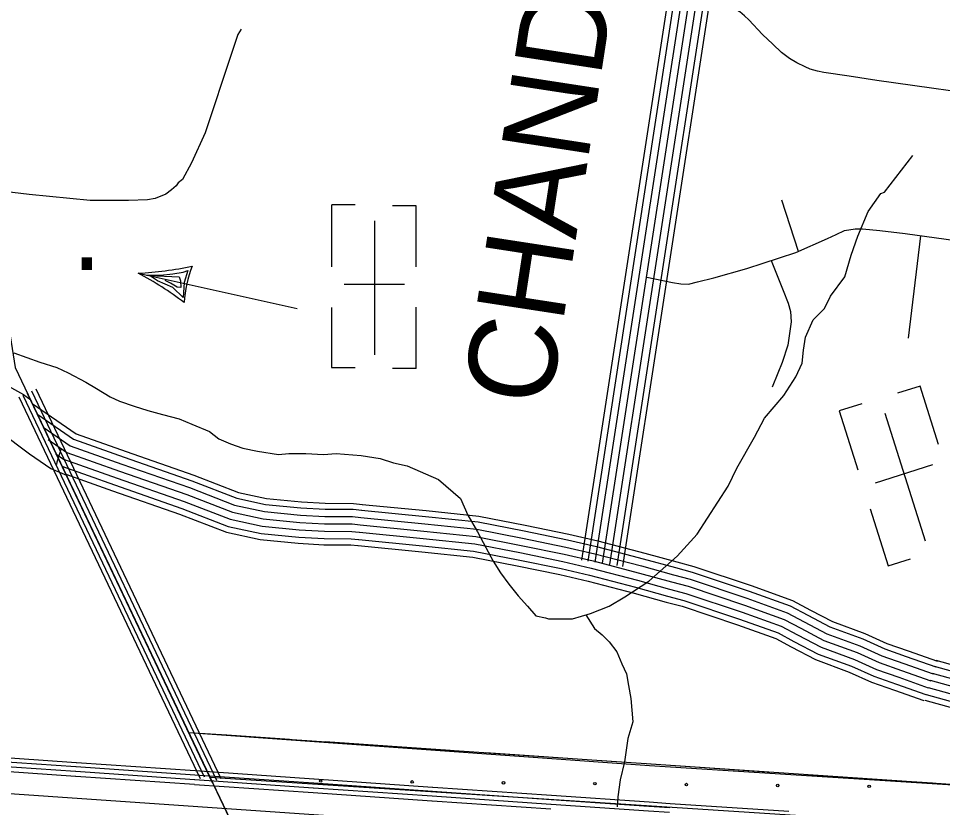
# Model space of a CAD drawing. Extents: x 1788175 to 1969470, y 584502 to 738744.
# Drawn here: x 1799965 to 1803852, y 668600 to 671917 of the extents above; entities that cross this region are included whole.
import ezdxf

# ---------------------------------------------------------------- set-up
doc = ezdxf.new("R2010")
doc.units = 0
for name, color, linetype in [('DESIGN - EROSION CONTROL - Devices', 7, 'Continuous'), ('DESIGN - ROW - Right-of-Way and Easement Labels', 7, 'Continuous'), ('DESIGN - SCRATCH - User 1', 7, 'Continuous'), ('DESIGN - TRANSPORTATION - Text', 7, 'Continuous'), ('DESIGN - UTILITIES - Cable (Overhead) with Text', 7, 'Continuous'), ('DESIGN - UTILITIES - Cable (Underground) with Text', 7, 'Continuous'), ('SURVEY - CENTERLINE - Preliminary', 7, 'Continuous'), ('SURVEY - CONTROL with Text', 7, 'Continuous'), ('SURVEY - DRAINAGE - Natural Features', 7, 'Continuous'), ('SURVEY - TRANSPORTATION - Roads', 7, 'Continuous'), ('SURVEY - VEGETATION - Features with Text', 7, 'Continuous')]:
    doc.layers.add(name, color=color, linetype=linetype)

msp = doc.modelspace()

# ---------------------------------------------------------------- linework, layer by layer
at = {"layer": 'DESIGN - EROSION CONTROL - Devices'}
for centre in [(1801236.5, 668710.8), (1801621, 668707.1), (1802005.6, 668703.4), (1802390.1, 668699.6), (1802774.7, 668695.9), (1803159.2, 668692.2), (1803543.8, 668688.4)]:
    msp.add_circle(centre, 5.28, dxfattribs=at)
at = {"layer": 'DESIGN - SCRATCH - User 1'}
for points in [[(1808664.9, 668387), (1806557.8, 668530), (1805384.9, 668598.1), (1804466.6, 668656.6), (1803677.1, 668706.8), (1802620.2, 668775.3), (1800681.4, 668914), (1800770.3, 668727.1)], [(1800770.3, 668727.1), (1809434.2, 668164.9), (1810234.9, 668118.5)]]:
    msp.add_lwpolyline(points, dxfattribs=at)
at = {"layer": 'DESIGN - TRANSPORTATION - Text'}
for points in [[(1802950.4, 669950.2), (1802986.8, 670026.5), (1803061, 670156.3), (1803103.1, 670236.1), (1803185.2, 670331.9), (1803235.3, 670409.8), (1803261.4, 670467.7), (1803267.5, 670521.7), (1803275.6, 670577.6), (1803307.7, 670649.5), (1803355.7, 670697.4), (1803381.8, 670749.3), (1803441.9, 670831.2), (1803468, 670921), (1803496.1, 671000.9), (1803540.3, 671104.8), (1803592.4, 671180.6), (1803608.4, 671186.6), (1803727.6, 671341)], [(1799945.3, 670510.8), (1800055.3, 670471.2), (1800125.8, 670449.2), (1800174.2, 670427.2), (1800249, 670387.5), (1800293, 670361.1), (1800350.3, 670325.9), (1800389.9, 670308.3), (1800451.5, 670286.3), (1800508.8, 670268.7), (1800570.4, 670251.1), (1800640.8, 670233.5), (1800693.7, 670211.5), (1800768.5, 670180.6), (1800808.1, 670149.8), (1800856.5, 670127.8), (1800909.4, 670110.2), (1800971, 670097), (1801059, 670083.8), (1801103.1, 670088.2), (1801173.5, 670088.2), (1801248.3, 670083.8), (1801301.2, 670088.2), (1801406.8, 670079.4), (1801486.1, 670066.2), (1801543.3, 670048.6), (1801600.5, 670035.4), (1801732.6, 669978.1), (1801825, 669898.9), (1801855.9, 669828.5), (1801895.5, 669758), (1801930.7, 669692), (1801961.5, 669634.8), (1801992.3, 669586.3), (1802027.5, 669537.9), (1802067.2, 669489.5), (1802106.8, 669445.5), (1802142, 669405.8), (1802181.6, 669397), (1802194.8, 669392.6), (1802230.1, 669392.6), (1802296.1, 669392.6), (1802370.9, 669414.6), (1802450.2, 669445.5), (1802516.2, 669485.1), (1802617.5, 669551.1), (1802736.3, 669656.8), (1802820, 669749.2), (1802950.4, 669950.2)], [(1802352.3, 669409.2), (1802388, 669351.8), (1802419.9, 669325.8), (1802449.8, 669295.8), (1802481.8, 669253.8), (1802503.7, 669203.8), (1802523.6, 669161.8), (1802531.5, 669111.9), (1802541.4, 669057.9), (1802549.3, 668960), (1802529.2, 668890.1), (1802515, 668792.2), (1802496.9, 668716.3), (1802486.8, 668644.4), (1802484, 668602.9)]]:
    msp.add_lwpolyline(points, dxfattribs=at)
at = {"layer": 'DESIGN - UTILITIES - Cable (Overhead) with Text'}
for p, q in [((1800469.1, 670845.4), (1801137.4, 670698)), ((1800503.5, 670837.7), (1800562, 670837.8)), ((1800550.3, 670814.4), (1800516.1, 670836)), ((1800516.1, 670836), (1800641.7, 670830)), ((1800562, 670837.8), (1800614.1, 670842.6)), ((1800614.1, 670842.6), (1800658.1, 670850.3)), ((1800641.7, 670830), (1800646.8, 670813.8)), ((1800658.1, 670850.3), (1800677.9, 670856.7)), ((1800677.9, 670856.7), (1800662.6, 670807)), ((1800614.4, 670785.1), (1800550.3, 670814.4)), ((1800604.4, 670803.6), (1800581.9, 670815)), ((1800633.3, 670787.4), (1800604.4, 670803.6)), ((1800646.8, 670813.8), (1800648.3, 670786.3)), ((1800662.6, 670807), (1800658.4, 670743.9)), ((1800658.4, 670743.9), (1800614.4, 670785.1)), ((1800648.3, 670786.3), (1800633.3, 670787.4))]:
    msp.add_line(p, q, dxfattribs=at)
for centre, radius, start, end in [((1800378.5, 672395), 1552.3, 273.3481, 281.7759), ((1801192.7, 670685.8), 532.3, 159.1314, 175.9898), ((1799824.3, 669618.1), 1386.4, 52.8398, 62.2784)]:
    msp.add_arc(centre, radius, start, end, dxfattribs=at)
at = {"layer": 'DESIGN - UTILITIES - Cable (Underground) with Text'}
for p, q in [((1801282.4, 671132.8), (1801282.4, 670872)), ((1801382, 671132.8), (1801283, 671132.8)), ((1801638.7, 671128.9), (1801539, 671128.9)), ((1801638.6, 670872.1), (1801638.6, 671128.9)), ((1801588.6, 670797.7), (1801335, 670797.7)), ((1801282.4, 670701), (1801282.4, 670449.6)), ((1801638.6, 670445.6), (1801638.6, 670703.7)), ((1801282.5, 670449.6), (1801380.8, 670449.6)), ((1801638.5, 670445.6), (1801539, 670445.6)), ((1803758.5, 670370.8), (1803663.3, 670340.8)), ((1803835.7, 670126), (1803758.4, 670370.8)), ((1803512.5, 670297.3), (1803418, 670267.5)), ((1803417.5, 670267.3), (1803496, 670018.6)), ((1803810.4, 670040), (1803568.5, 669963.6)), ((1803547.4, 669855.6), (1803623.2, 669615.8)), ((1803623.3, 669615.8), (1803717, 669645.4))]:
    msp.add_line(p, q, dxfattribs=at)
for points in [[(1801463.3, 671065.4), (1801463.3, 670502.4)], [(1803610.3, 670257.5), (1803779.8, 669720.7)]]:
    msp.add_lwpolyline(points, dxfattribs=at)
at = {"layer": 'SURVEY - CENTERLINE - Preliminary'}
for points in [[(1820911.6, 669976.1), (1819959.6, 669862.9), (1819285.6, 669778.9), (1818471.7, 669687.3), (1818197.7, 669646.1), (1817901.7, 669609), (1817647.6, 669569.8), (1817303.6, 669516.8), (1816595.4, 669363), (1813251.8, 668401.6), (1812821.5, 668274.9), (1812669.5, 668231.4), (1812114.7, 668085.6), (1811965.2, 668057.6), (1811725.2, 668016.3), (1811385.2, 667981.3), (1811049.3, 667954.3), (1810455.5, 667960), (1806509.9, 668228.8), (1805310.6, 668298.1), (1804431.1, 668354.5), (1803641.6, 668404.7), (1802608.2, 668471.6), (1798199.8, 668776.1)], [(1799709.4, 668823.7), (1800208.2, 668789.2)], [(1799706.8, 668786.2), (1800205.6, 668751.8)], [(1799708.2, 668806.2), (1800207, 668771.7)], [(1800207.9, 668771.7), (1800706.7, 668737.2)], [(1800209.1, 668789.1), (1800707.9, 668754.7)], [(1799706.3, 668765.9), (1800205.2, 668731.5)], [(1800206.1, 668731.4), (1800704.9, 668697)], [(1800206.6, 668751.7), (1800705.4, 668717.3)], [(1800707.6, 668737.2), (1801206.5, 668702.7)], [(1800708.9, 668754.6), (1801207.7, 668720.2)], [(1800705.8, 668696.9), (1801204.6, 668662.4)], [(1800706.3, 668717.2), (1801205.1, 668682.7)], [(1801207.4, 668702.6), (1801706.2, 668668.2)], [(1801208.6, 668720.1), (1801707.4, 668685.6)], [(1801205.5, 668662.4), (1801704.3, 668627.9)], [(1801206, 668682.7), (1801704.8, 668648.2)], [(1801707.1, 668668.1), (1802205.9, 668633.6)], [(1801708.3, 668685.6), (1802207.1, 668651.1)], [(1802208, 668651), (1802618.3, 668622.7), (1802706.2, 668617)], [(1801705.2, 668627.8), (1802204, 668593.4)], [(1801705.7, 668648.1), (1802204.5, 668613.7)], [(1802205.4, 668613.6), (1802615.8, 668585.3), (1802703.8, 668579.6)], [(1802206.8, 668633.6), (1802617.1, 668605.2), (1802705, 668599.5)], [(1802707.1, 668616.9), (1803206, 668584.7)]]:
    msp.add_lwpolyline(points, dxfattribs=at)
at = {"layer": 'SURVEY - CONTROL with Text'}
for points in [[(1797699.2, 670443), (1797810.6, 670429.8), (1798058.7, 670432.9), (1798127.3, 670439.7), (1798206.8, 670457.6), (1798263.5, 670474.6), (1798354.5, 670516.8), (1798434, 670547.4), (1798470.8, 670557.1), (1798572, 670579.1), (1798685, 670605.8), (1798773.7, 670598.8), (1798911.1, 670598.4), (1799115.6, 670547.7), (1799248.6, 670545.4), (1799466, 670515.5), (1799572.7, 670490.6), (1799661.8, 670472.5), (1799740.7, 670455.6), (1799813.4, 670416.8), (1799884.2, 670392.3), (1799986.1, 670335.4), (1800016.6, 670312.8)], [(1800022.4, 670298.5), (1800208, 670170.5), (1800418.6, 670095.9), (1800703.4, 669996.8), (1800890.2, 669924.2), (1801008.3, 669898.4), (1801155.5, 669884.6), (1801255.5, 669878.6), (1801373.8, 669878.2), (1801412.2, 669873.9)], [(1800046.7, 670251.8), (1800196.6, 670148.3), (1800410.4, 670072.6), (1800694.8, 669973.6), (1800883.1, 669900.5), (1801004.5, 669874), (1801153.6, 669860), (1801254.8, 669853.9), (1801372.4, 669853.5), (1801409.4, 669849.3)], [(1799885.5, 670179.7), (1800011.5, 670086.1), (1800101.6, 670024.4), (1800167.6, 669996.8)], [(1800073.6, 670195.5), (1800182.4, 670120.4), (1800400.1, 670043.3), (1800684.1, 669944.5), (1800874.1, 669870.7), (1800999.7, 669843.3), (1801151.3, 669829.1), (1801253.8, 669822.9), (1801370.6, 669822.5), (1801405.9, 669818.5)], [(1800090.2, 670146.4), (1800168.2, 670092.6), (1800389.8, 670014.1), (1800673.4, 669915.4), (1800865.1, 669840.9), (1800995, 669812.6), (1801148.9, 669798.2), (1801252.8, 669791.9), (1801368.8, 669791.5), (1801402.4, 669787.7)], [(1800122.7, 670086.3), (1800153.9, 670064.7), (1800379.6, 669984.8), (1800662.7, 669886.3), (1800856.1, 669811.1), (1800990.2, 669781.9), (1801146.5, 669767.2), (1801251.8, 669760.9), (1801367, 669760.6), (1801398.9, 669756.9)], [(1800147.7, 670034.1), (1800369.3, 669955.6), (1800652, 669857.2), (1800847.2, 669781.4), (1800985.4, 669751.2), (1801144.1, 669736.3), (1801250.8, 669729.9), (1801365.2, 669729.6), (1801395.4, 669726.1)], [(1800163.9, 670001), (1800360.8, 669931.3), (1800643.1, 669833), (1800839.7, 669756.7), (1800981.5, 669725.7), (1801142.1, 669710.7), (1801250, 669704.2), (1801363.7, 669703.8), (1801392.5, 669700.6)], [(1801410.7, 669874), (1801679.5, 669848.2), (1801902.2, 669824.5), (1802096.9, 669786.5), (1802279.7, 669749), (1802402.8, 669720.6), (1802599.9, 669669), (1802734.9, 669631.8), (1802806.8, 669612.6), (1803047.5, 669532.3), (1803221.7, 669469.4), (1803296.7, 669429.5), (1803389, 669381.1), (1803526, 669330.9), (1803618.4, 669289.3), (1803707.9, 669257.9), (1803831.8, 669214.4)], [(1801405.4, 669818.6), (1801673.9, 669792.8), (1801893.9, 669769.4), (1802086, 669731.9), (1802267.8, 669694.6), (1802389.5, 669666.5), (1802585.4, 669615.2), (1802720.3, 669578), (1802790.8, 669559.2), (1803029.2, 669479.7), (1803199, 669418.4), (1803270.6, 669380.2), (1803366.4, 669330.1), (1803505, 669279.2), (1803597.7, 669237.5), (1803689.5, 669205.4), (1803813.3, 669161.8)], [(1801408.4, 669849.4), (1801677, 669823.6), (1801898.5, 669800), (1802092.1, 669762.3), (1802274.4, 669724.9), (1802396.9, 669696.6), (1802593.5, 669645.1), (1802728.4, 669607.9), (1802799.7, 669588.9), (1803039.4, 669509), (1803211.7, 669446.8), (1803285.1, 669407.6), (1803378.9, 669358.5), (1803516.7, 669308), (1803609.3, 669266.3), (1803699.8, 669234.6), (1803823.6, 669191.1)], [(1801402.4, 669787.7), (1801670.7, 669761.9), (1801889.3, 669738.7), (1802079.9, 669701.5), (1802261.2, 669664.3), (1802382.1, 669636.4), (1802577.4, 669585.3), (1802712.2, 669548.1), (1802781.9, 669529.5), (1803019, 669450.4), (1803186.4, 669390), (1803256.1, 669352.8), (1803353.8, 669301.6), (1803493.3, 669250.5), (1803586.2, 669208.7), (1803679.2, 669176.1), (1803803, 669132.6)], [(1801399.5, 669756.9), (1801667.6, 669731.1), (1801884.6, 669708), (1802073.8, 669671.1), (1802254.6, 669634), (1802374.7, 669606.3), (1802569.3, 669555.3), (1802704.1, 669518.1), (1802773, 669499.8), (1803008.9, 669421.1), (1803173.8, 669361.6), (1803241.7, 669325.4), (1803341.2, 669273.2), (1803481.6, 669221.8), (1803574.7, 669179.8), (1803669, 669146.9), (1803792.7, 669103.3)], [(1801396.5, 669726), (1801664.5, 669700.2), (1801880, 669677.3), (1802067.7, 669640.7), (1802248, 669603.7), (1802367.3, 669576.2), (1802561.3, 669525.4), (1802696, 669488.2), (1802764.1, 669470), (1802998.7, 669391.8), (1803161.2, 669333.2), (1803227.2, 669298), (1803328.6, 669244.8), (1803469.8, 669193.1), (1803563.2, 669151), (1803658.7, 669117.6), (1803782.4, 669074.1)], [(1801394, 669700.4), (1801661.9, 669674.7), (1801876.2, 669651.9), (1802062.7, 669615.5), (1802242.5, 669578.6), (1802361.1, 669551.2), (1802554.6, 669500.5), (1802689.2, 669463.4), (1802756.7, 669445.4), (1802990.3, 669367.5), (1803150.7, 669309.6), (1803215.2, 669275.2), (1803318.2, 669221.3), (1803460.1, 669169.2), (1803553.7, 669127.1), (1803650.2, 669093.3), (1803773.9, 669049.8)], [(1806246.9, 668859.4), (1806111.8, 668890.9), (1805987.6, 668925.9), (1805845.8, 668972.2), (1805765.7, 668999.7), (1805640.3, 669022.3), (1805500, 669039.2), (1804998.6, 669065), (1804704, 669074.3), (1804514.4, 669076.6), (1804346.8, 669094.7), (1804212.1, 669110.2), (1803825.7, 669217.4)], [(1806234.1, 668804.2), (1806097.6, 668835.9), (1805971.1, 668871.6), (1805827.8, 668918.4), (1805751.4, 668944.7), (1805631.9, 668966.2), (1805495.1, 668982.7), (1804996.3, 669008.3), (1804702.8, 669017.6), (1804511, 669019.9), (1804340.5, 669038.4), (1804201.2, 669054.4), (1803810.6, 669162.7)], [(1806241.1, 668834.4), (1806105.3, 668866), (1805980.1, 668901.3), (1805837.6, 668947.8), (1805759.2, 668974.7), (1805636.5, 668996.8), (1805497.8, 669013.6), (1804997.6, 669039.3), (1804703.4, 669048.6), (1804512.9, 669050.9), (1804344, 669069.2), (1804207.2, 669084.9), (1803818.8, 669192.6)], [(1806227, 668774), (1806089.9, 668805.9), (1805962, 668841.9), (1805817.9, 668889), (1805743.5, 668914.6), (1805627.3, 668935.5), (1805492.5, 668951.8), (1804995, 668977.3), (1804702.1, 668986.6), (1804509.1, 668989), (1804337.1, 669007.6), (1804195.3, 669023.8), (1803802.3, 669132.8)], [(1806220, 668743.8), (1806082.2, 668775.9), (1805953, 668812.3), (1805808.1, 668859.6), (1805735.7, 668884.5), (1805622.7, 668904.8), (1805489.8, 668920.9), (1804993.7, 668946.4), (1804701.4, 668955.6), (1804507.3, 668958), (1804333.7, 668976.7), (1804189.4, 668993.3), (1803794, 669103)], [(1806207.4, 668689.5), (1806068.3, 668721.9), (1805936.8, 668758.9), (1805790.4, 668806.8), (1805721.6, 668830.4), (1805614.4, 668849.7), (1805485, 668865.3), (1804991.4, 668890.7), (1804700.2, 668899.9), (1804503.9, 668902.3), (1804327.5, 668921.4), (1804178.7, 668938.5), (1803779.1, 669049.3)], [(1806213, 668713.6), (1806074.5, 668745.8), (1805944, 668782.6), (1805798.2, 668830.2), (1805727.9, 668854.4), (1805618.1, 668874.2), (1805487.2, 668890), (1804992.4, 668915.4), (1804700.7, 668924.6), (1804505.4, 668927), (1804330.2, 668945.9), (1804183.4, 668962.8), (1803785.7, 669073.1)]]:
    msp.add_lwpolyline(points, dxfattribs=at)
at = {"layer": 'SURVEY - DRAINAGE - Natural Features'}
for points in [[(1798659.4, 677936.4), (1798896.4, 677126.1), (1799951.3, 670448.8), (1800796.6, 668671.9)], [(1800730.4, 668720.3), (1799967.5, 670324)], [(1800748, 668727.6), (1799984.7, 670332.1)], [(1800781.6, 668703.4), (1800002.8, 670340.7)], [(1800799.4, 668712.5), (1800020.8, 670349.3)], [(1800817.7, 668720.7), (1800038.9, 670357.9)], [(1800796.6, 668671.9), (1800870.5, 668516.4), (1801790.7, 666582.1), (1804306.1, 660246.3), (1805349.3, 660113.5), (1805298.3, 659806), (1805817.9, 659738.6), (1805779.3, 659532.9), (1805742.6, 659289.3), (1805728.5, 659251.4), (1805718.4, 659235.4), (1805700.3, 659207.5), (1805682.3, 659193.6), (1805652.3, 659177.7), (1805588.3, 659165.9), (1805382.4, 659182.4), (1804803.3, 659244.6)]]:
    msp.add_lwpolyline(points, dxfattribs=at)
at = {"layer": 'SURVEY - TRANSPORTATION - Roads'}
for points in [[(1803778.6, 674841.6), (1803798.9, 674750.6), (1803783.7, 674611.6), (1803750.8, 674153.8), (1803669.5, 673475.6), (1803626.7, 673044.2), (1803613.8, 672931.9), (1803599.6, 672887.1), (1803587.9, 672854.5), (1803552, 672783.2), (1803492.8, 672757.4), (1803432.2, 672746.4), (1803373.6, 672754.1), (1803319.2, 672766.7), (1803141.3, 672804.9), (1803097.2, 672815.1), (1803071.7, 672813.9), (1803031.4, 672801.5), (1803007.4, 672783.6), (1802994.4, 672774.3), (1802966.1, 672697.8), (1802915.3, 672484.7), (1802854.8, 672039.7), (1802482.2, 669616.8)], [(1803802.6, 674847.5), (1803823.9, 674751.9), (1803808.3, 674609.4), (1803775.4, 674151.4), (1803694.1, 673472.9), (1803651.3, 673041.6), (1803638.1, 672926.6), (1803623, 672879.1), (1803610.6, 672844.7), (1803570.1, 672764.1), (1803500, 672733.6), (1803432.8, 672721.4), (1803369.2, 672729.8), (1803313.9, 672742.6), (1803136, 672780.8), (1803095, 672790.3), (1803075.9, 672789.4), (1803042.8, 672779.2), (1803022, 672763.6), (1803014.9, 672758.6), (1802989.8, 672690.6), (1802939.6, 672480.1), (1802879.3, 672036.1), (1802506.6, 669613)], [(1802706.6, 672061.1), (1802334.2, 669639.6)], [(1802732.1, 672057.4), (1802359.6, 669635.7)], [(1802762.8, 672053), (1802390.3, 669630.9)], [(1802793.5, 672048.5), (1802420.9, 669626.2)], [(1802793.5, 672048.5), (1802420.9, 669626.2)], [(1802824.1, 672044.1), (1802451.6, 669621.5)], [(1804656.1, 671505.2), (1803576.4, 671655.5), (1803460.2, 671674.4), (1803353.1, 671689.5), (1803325.8, 671695.2), (1803295.5, 671704), (1803274.2, 671713.8), (1803239.8, 671729.6), (1803208.4, 671748.3), (1803174.9, 671774.1), (1803138.4, 671808.9), (1803094.7, 671849.6), (1803037.7, 671911.3), (1803019.5, 671928.2), (1802999.2, 671944.1), (1802973.8, 671958.9), (1802943.5, 671971.7), (1802903, 671983.3), (1802873.7, 671988.1), (1802843.4, 671990.8), (1802786.4, 672002)], [(1800901.9, 671872.2), (1800887.6, 671848.8), (1800861.5, 671768.9), (1800750.9, 671435.3), (1800692.7, 671309.5), (1800654.5, 671239.6), (1800636.5, 671225.6), (1800628.5, 671213.7), (1800608.5, 671195.7), (1800584.4, 671177.7), (1800540.4, 671159.8), (1800508.4, 671153.8), (1800428.4, 671151.9), (1800266.5, 671152.1), (1800010.6, 671176.4), (1799774.2, 671204.6)], [(1803247, 670937.7), (1803175.8, 671152.3)], [(1802607.8, 670829.1), (1802716.7, 670806.1), (1802751.2, 670800.7), (1802784, 670800.4), (1802821.3, 670810), (1802889.7, 670826), (1803029.4, 670866), (1803235.7, 670932.6), (1803368, 670992.4), (1803405.4, 671008), (1803439.7, 671025.1), (1803484.9, 671032.9), (1803515.2, 671032.5), (1803588.4, 671025.8), (1803694.8, 671012.5), (1804274.3, 670933.3)], [(1803759.9, 671003.6), (1803708.2, 670573)], [(1803131.9, 670899.1), (1803182.5, 670772.8), (1803202.4, 670719.5), (1803212.3, 670685.3), (1803215.4, 670641.7), (1803209.1, 670593), (1803201.4, 670543.5), (1803178, 670470.2), (1803159.3, 670425), (1803135.9, 670366.6)], [(1800144.6, 670108.8), (1800126.5, 670051.3), (1800124.4, 670041)]]:
    msp.add_lwpolyline(points, dxfattribs=at)
at = {"layer": 'SURVEY - VEGETATION - Features with Text'}
for points in [[(1808959.9, 668367), (1808664.9, 668387), (1806557.8, 668530), (1804466.6, 668656.6), (1800681.4, 668914), (1800969.8, 668307.9)], [(1800841.6, 668903.1), (1800681.4, 668914), (1800725.9, 668820.6)], [(1801105, 668885.2), (1800841.6, 668903.1)], [(1801518, 668857.1), (1801254.6, 668875)], [(1801781.4, 668839.2), (1801518, 668857.1)], [(1802194.5, 668811.1), (1801931.1, 668829)], [(1802457.9, 668793.2), (1802194.5, 668811.1)], [(1802870.9, 668765.1), (1802607.5, 668783)], [(1803134.3, 668747.2), (1802870.9, 668765.1)], [(1803547.3, 668719.1), (1803283.9, 668737.1)], [(1803810.7, 668701.2), (1803547.3, 668719.1)]]:
    msp.add_lwpolyline(points, dxfattribs=at)

# ---------------------------------------------------------------- texts
at = {"layer": 'DESIGN - ROW - Right-of-Way and Easement Labels'}
msp.add_text('CHANDLER', height=370, rotation=81.2565, dxfattribs=at).set_placement((1802200.3, 670277.1))
at = {"layer": 'DESIGN - UTILITIES - Cable (Underground) with Text'}
msp.add_text('.', height=343, dxfattribs=at).set_placement((1800188.9, 670858.8))

doc.saveas('drawing.dxf')
